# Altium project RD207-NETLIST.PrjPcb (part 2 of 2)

## Sheet 7.SchDoc
size 420 x 297 mm
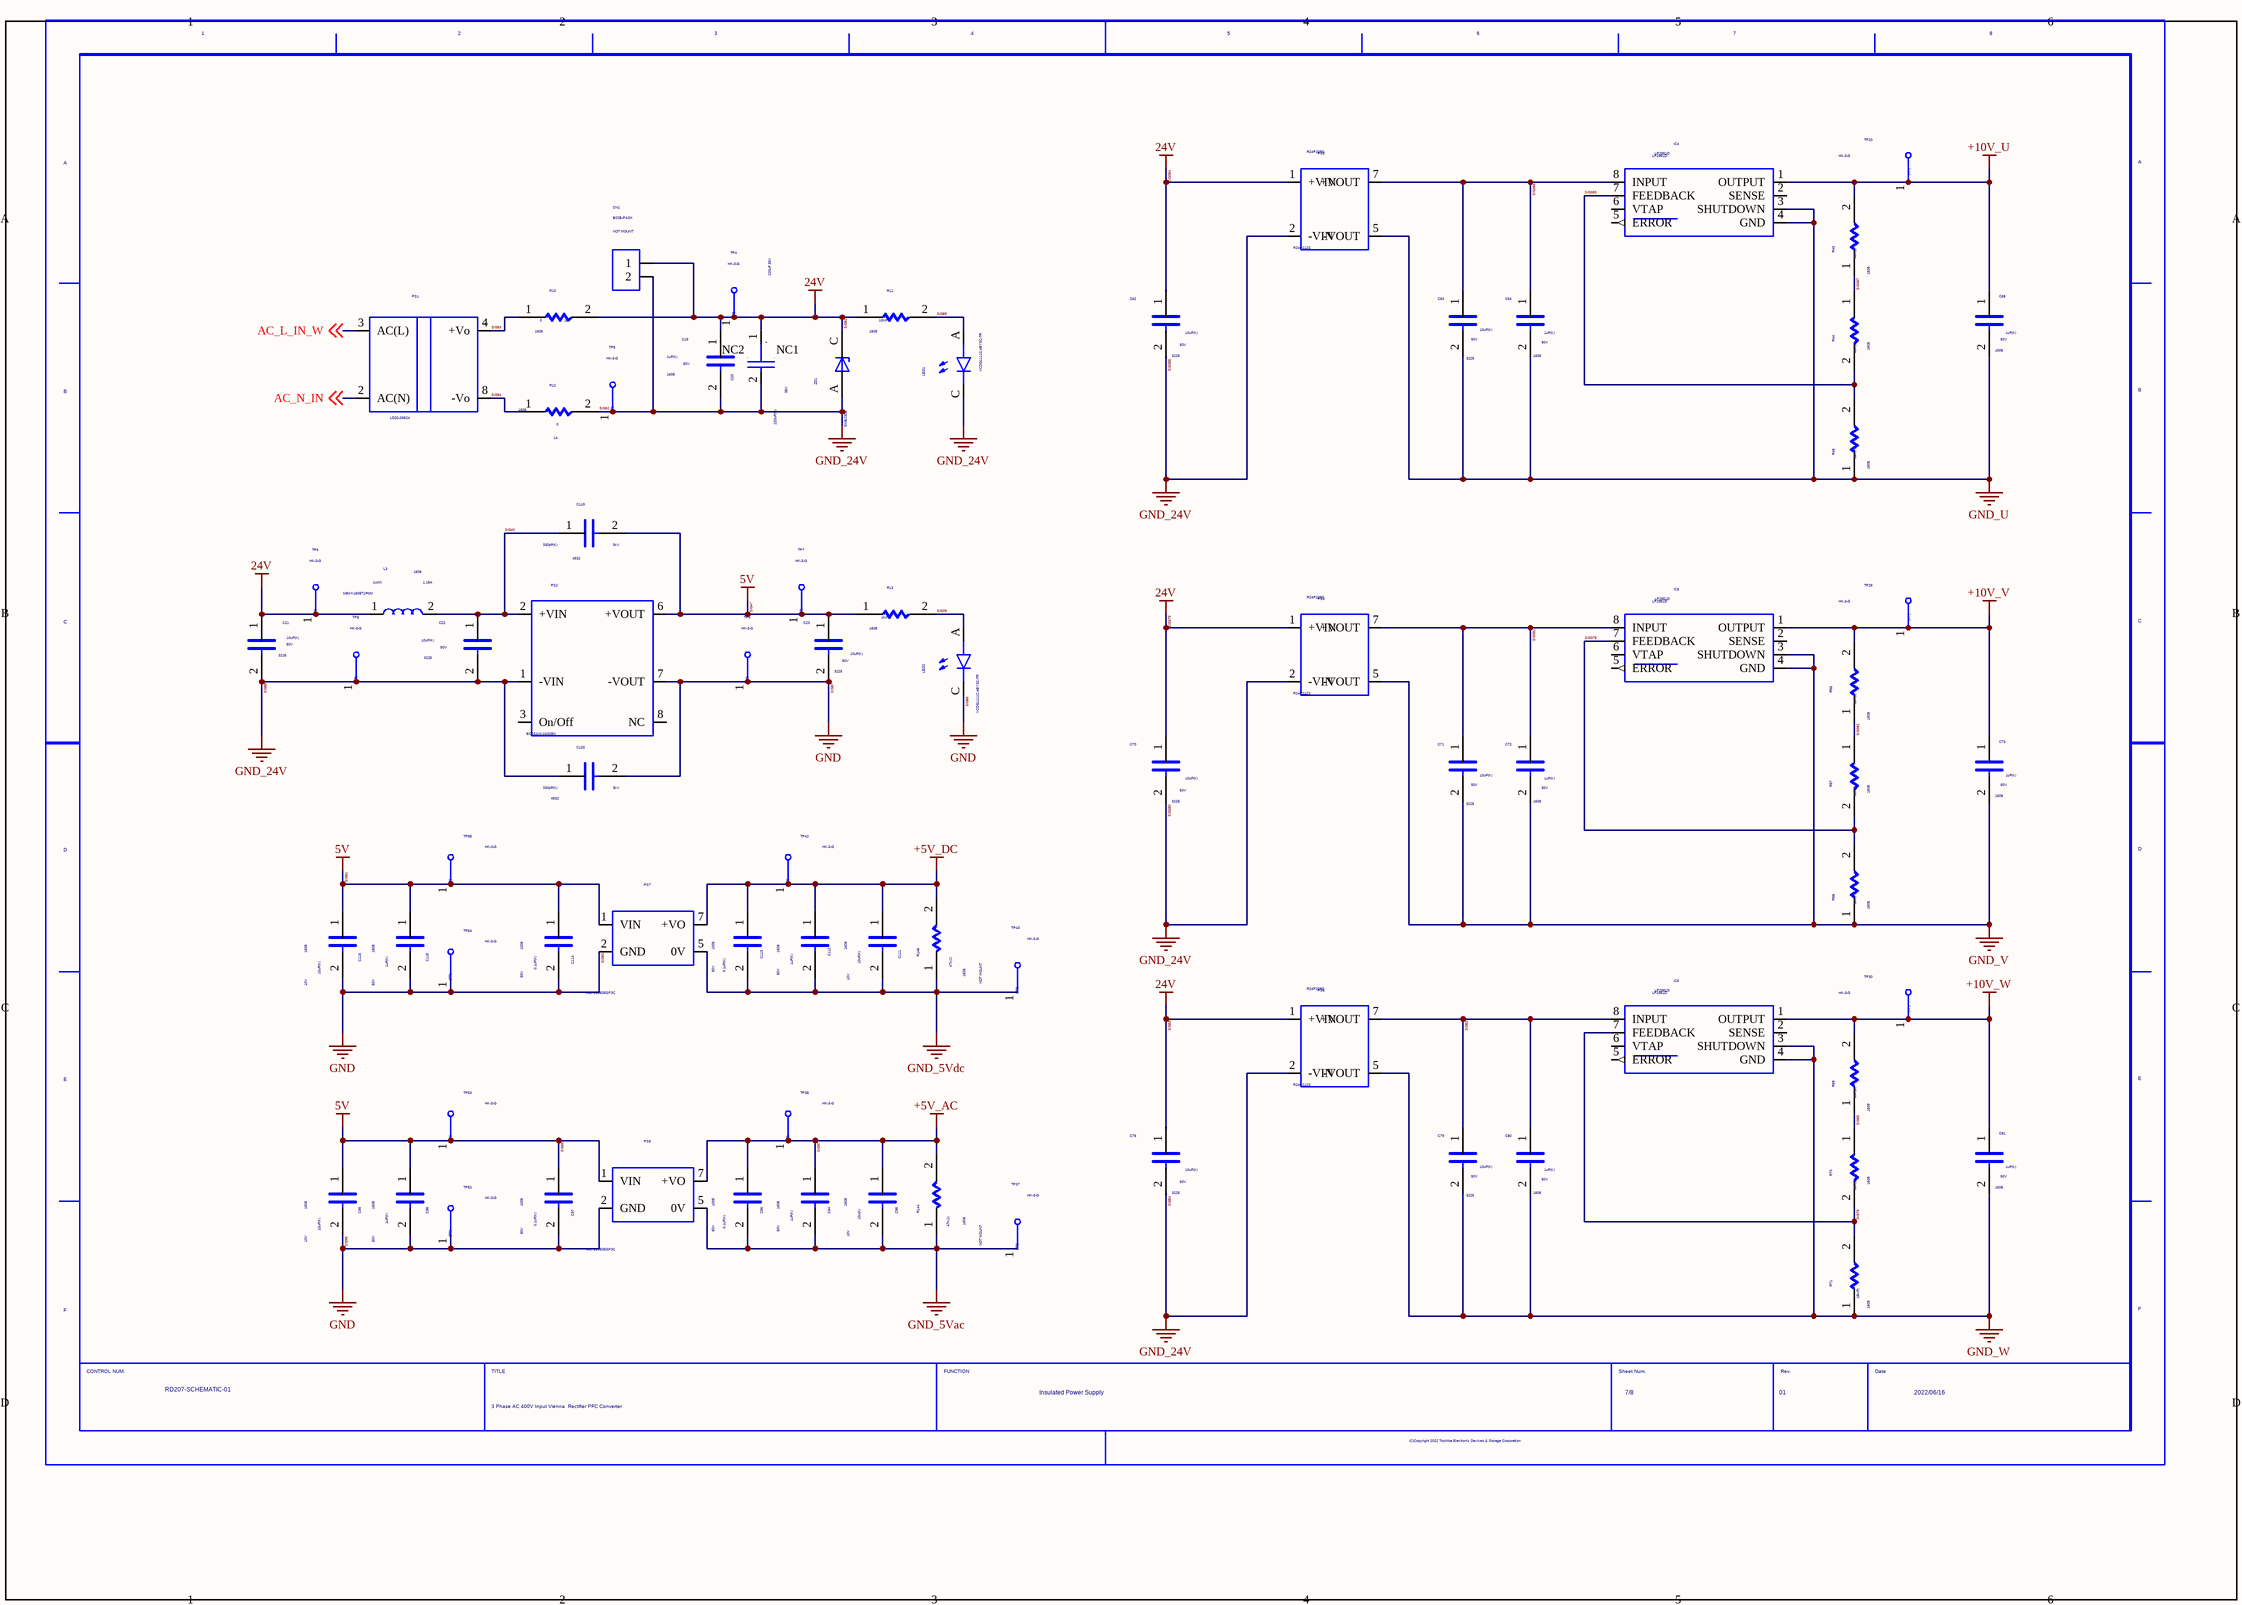
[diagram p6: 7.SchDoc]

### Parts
(Parts that share a designator on the sheet are numbered #1, #2 ... from top to bottom, then left to right.)
C19  SIZECODESMD: 1608  VAL2: 50V  VAL1: 1uF(K)  (hidden comment: C)
C20  NOTE: 220uF 35V  VAL2: 35V  VAL1: 220uF(M)  (hidden comment: MAL216099001E3)
C21  SIZECODESMD: 3225  VAL2: 50V  VAL1: 10uF(K)  (hidden comment: C)
C22  SIZECODESMD: 3225  VAL2: 50V  VAL1: 10uF(K)  (hidden comment: C)
C23  SIZECODESMD: 3225  VAL2: 50V  VAL1: 10uF(K)  (hidden comment: C)
C62  SIZECODESMD: 3225  VAL2: 50V  VAL1: 10uF(K)  (hidden comment: C)
C63  SIZECODESMD: 3225  VAL2: 50V  VAL1: 10uF(K)  (hidden comment: C)
C64  SIZECODESMD: 1608  VAL2: 50V  VAL1: 1uF(K)  (hidden comment: C)
C65  SIZECODESMD: 1608  VAL2: 50V  VAL1: 1uF(K)  (hidden comment: C)
C70  SIZECODESMD: 3225  VAL2: 50V  VAL1: 10uF(K)  (hidden comment: C)
C71  SIZECODESMD: 3225  VAL2: 50V  VAL1: 10uF(K)  (hidden comment: C)
C72  SIZECODESMD: 1608  VAL2: 50V  VAL1: 1uF(K)  (hidden comment: C)
C73  SIZECODESMD: 1608  VAL2: 50V  VAL1: 1uF(K)  (hidden comment: C)
C78  SIZECODESMD: 3225  VAL2: 50V  VAL1: 10uF(K)  (hidden comment: C)
C79  SIZECODESMD: 3225  VAL2: 50V  VAL1: 10uF(K)  (hidden comment: C)
C80  SIZECODESMD: 1608  VAL2: 50V  VAL1: 1uF(K)  (hidden comment: C)
C81  SIZECODESMD: 1608  VAL2: 50V  VAL1: 1uF(K)  (hidden comment: C)
C94  SIZECODESMD: 1608  VAL2: 50V  VAL1: 1uF(K)  (hidden comment: C)
C95  SIZECODESMD: 1608  VAL2: 10V  VAL1: 10u(K)  (hidden comment: C)
C96  SIZECODESMD: 1005  VAL2: 50V  VAL1: 0.1uF(K)  (hidden comment: C)
C97  SIZECODESMD: 1005  VAL2: 50V  VAL1: 0.1uF(K)  (hidden comment: C)
C98  SIZECODESMD: 1608  VAL2: 50V  VAL1: 1uF(K)  (hidden comment: C)
C99  SIZECODESMD: 1608  VAL2: 10V  VAL1: 10uF(K)  (hidden comment: C)
C111  SIZECODESMD: 1608  VAL2: 10V  VAL1: 10uF(K)  (hidden comment: C)
C112  SIZECODESMD: 1608  VAL2: 50V  VAL1: 1uF(K)  (hidden comment: C)
C113  SIZECODESMD: 1005  VAL2: 50V  VAL1: 0.1uF(K)  (hidden comment: C)
C114  SIZECODESMD: 1005  VAL2: 50V  VAL1: 0.1uF(K)  (hidden comment: C)
C115  SIZECODESMD: 1608  VAL2: 50V  VAL1: 1uF(K)  (hidden comment: C)
C116  SIZECODESMD: 1608  VAL2: 10V  VAL1: 10uF(K)  (hidden comment: C)
C119  SIZECODESMD: 4532  VAL2: 3kV  VAL1: 330pF(K)  (hidden comment: C)
C120  SIZECODESMD: 4532  VAL2: 3kV  VAL1: 330pF(K)  (hidden comment: C)
CN1  NOTMOUNT: NOT MOUNT  (hidden comment: BM02B-PASS-1-TFT(LF)(SN))
IC4  LP2951D
IC5  LP2951D
IC6  LP2951D
L3  SIZECODESMD: 1608  VAL3: MBKK1608T1R0M  VAL2: 1.15A  VAL1: 1u(M)  (hidden comment: L)
LED1  VCDG1111C-4BY3C-TR
LED2  VCDG1111C-4BY3C-TR
PS1  LD20-26B24
PS2  EC5SAW-24S05N
PS3  R24P209D
PS4  R24P209D
PS5  R24P209D
PS6  MEF1S0505SP3C
PS7  MEF1S0505SP3C
R10  SIZECODESMD: 1608  VAL2: 1A  VAL1: 0  (hidden comment: R)
R11  SIZECODESMD: 1608  VAL1: 10k(F)  (hidden comment: R)
R12  SIZECODESMD: 1608  VAL2: 1A  VAL1: 0  (hidden comment: R)
R13  SIZECODESMD: 1608  VAL1: 1k(F)  (hidden comment: R)
R43  SIZECODESMD: 1608  VAL1: 68k(B)  (hidden comment: R)
R44  SIZECODESMD: 1608  VAL1: 68k(B)  (hidden comment: R)
R45  SIZECODESMD: 1608  VAL1: 18k(F)  (hidden comment: R)
R56  SIZECODESMD: 1608  VAL1: 68k(B)  (hidden comment: R)
R57  SIZECODESMD: 1608  VAL1: 68k(B)  (hidden comment: R)
R58  SIZECODESMD: 1608  VAL1: 18k(F)  (hidden comment: R)
R69  SIZECODESMD: 1608  VAL1: 68k(B)  (hidden comment: R)
R70  SIZECODESMD: 1608  VAL1: 68k(B)  (hidden comment: R)
R71  SIZECODESMD: 1608  VAL1: 18k(F)  (hidden comment: R)
R144  NOTMOUNT: NOT MOUNT  SIZECODESMD: 1608  VAL1: 47k(J)  (hidden comment: R)
R145  NOTMOUNT: NOT MOUNT  SIZECODESMD: 1608  VAL1: 47k(J)  (hidden comment: R)
TP4  VAL3: HK-3-G  (hidden comment: TP)
TP5  VAL3: HK-3-G  (hidden comment: TP)
TP6  VAL3: HK-3-G  (hidden comment: TP)
TP7  VAL3: HK-3-G  (hidden comment: TP)
TP8  VAL3: HK-3-G  (hidden comment: TP)
TP9  VAL3: HK-3-G  (hidden comment: TP)
TP20  VAL3: HK-3-G  (hidden comment: TP)
TP25  VAL3: HK-3-G  (hidden comment: TP)
TP30  VAL3: HK-3-G  (hidden comment: TP)
TP35  VAL3: HK-3-G  (hidden comment: TP)
TP37  VAL3: HK-3-G  (hidden comment: TP)
TP42  VAL3: HK-3-G  (hidden comment: TP)
TP43  VAL3: HK-3-G  (hidden comment: TP)
TP52  VAL3: HK-3-G  (hidden comment: TP)
TP53  VAL3: HK-3-G  (hidden comment: TP)
TP54  VAL3: HK-3-G  (hidden comment: TP)
TP55  VAL3: HK-3-G  (hidden comment: TP)
U?#7  DATE: 2022/06/16  TITLE: 3 Phase AC 400V Input Vienna / Rectifier PFC Converter  REVISION: 01  SHEETNUMBER: 7/8  FUNCTION: Insulated Power Supply  DRAWINGNUMBER: RD207-SCHEMATIC-01  (hidden comment: WAKU_DEF100)
ZD1  VAL3: SMBJ30A  (hidden comment: ZD)

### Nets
5V: C23.1 C97.1 C98.1 C99.1 C114.1 C115.1 C116.1 C119.2 PS2.6(+VOUT) PS6.1(VIN) PS7.1(VIN) R13.1 TP7.1 TP53.1 TP55.1  [also labelled SIG47, SIG81, SIG95]  [project net SIG104]
24V: C19.1 C20.1 C21.1 C62.1 C70.1 C78.1 CN1.1 L3.1 PS3.1(+VIN) PS4.1(+VIN) PS5.1(+VIN) R10.2 R11.1 TP4.1 TP6.1 ZD1.C  [also labelled SIG379, SIG384, SIG53, SIG91]  [project net SIG351]
+5V_AC: C94.1 C95.1 C96.1 PS6.7(+VO) R144.2 TP35.1  [also labelled SIG97]  [project net SIG153]
+5V_DC: C111.1 C112.1 C113.1 PS7.7(+VO) R145.2 TP42.1
+10V_U: C65.1 IC4.1(OUTPUT) R43.2 TP20.1  [project net SIG287]
+10V_V: C73.1 IC5.1(OUTPUT) R56.2 TP25.1
+10V_W: C81.1 IC6.1(OUTPUT) R69.2 TP30.1
GND: C23.2 C97.2 C98.2 C99.2 C114.2 C115.2 C116.2 C120.2 LED2.C PS2.7(-VOUT) PS6.2(GND) PS7.2(GND) TP9.1 TP52.1 TP54.1  [also labelled SIG83, SIG86, SIG87, SIG96]  [project net SIG105]
GND_5Vac: C94.2 C95.2 C96.2 PS6.5(0V) R144.1 TP37.1
GND_5Vdc: C111.2 C112.2 C113.2 PS7.5(0V) R145.1 TP43.1
GND_24V: C19.2 C20.2 C21.2 C22.2 C62.2 C70.2 C78.2 C120.1 CN1.2 LED1.C PS2.1(-VIN) PS3.2(-VIN) PS4.2(-VIN) PS5.2(-VIN) R12.2 TP5.1 TP8.1 ZD1.A  [also labelled SIG380, SIG385, SIG54, SIG88, SIG92]  [project net SIG348]
GND_U: C63.2 C64.2 C65.2 IC4.3(SHUTDOWN) IC4.4(GND) PS3.5(-VOUT) R45.1
GND_V: C71.2 C72.2 C73.2 IC5.3(SHUTDOWN) IC5.4(GND) PS4.5(-VOUT) R58.1
GND_W: C79.2 C80.2 C81.2 IC6.3(SHUTDOWN) IC6.4(GND) PS5.5(-VOUT) R71.1
AC_L_IN_W: PS1.3(AC(L)) ; off-sheet AC_L_IN_W
AC_N_IN: PS1.2(AC(N)) ; off-sheet AC_N_IN
SIG39: LED2.A R13.2
SIG40: C22.1 C119.1 L3.2 PS2.2(+VIN)
SIG52: C79.1 C80.1 IC6.8(INPUT) PS5.7(+VOUT)
SIG55: R69.1 R70.1
SIG75: IC6.7(FEEDBACK) R70.2 R71.2
SIG89: LED1.A R11.2
SIG93: PS1.4(+Vo) R10.1
SIG94: PS1.8(-Vo) R12.1
SIG378: IC5.7(FEEDBACK) R57.2 R58.2
SIG381: C71.1 C72.1 IC5.8(INPUT) PS4.7(+VOUT)
SIG382: R56.1 R57.1
SIG383: IC4.7(FEEDBACK) R44.2 R45.2
SIG386: C63.1 C64.1 IC4.8(INPUT) PS3.7(+VOUT)
SIG387: R43.1 R44.1

Not connected (* = marked no-connect by the designer): C20 NC1 NC2; IC4 2(SENSE) 5(ERROR) 6(VTAP); IC5 2(SENSE) 5(ERROR) 6(VTAP); IC6 2(SENSE) 5(ERROR) 6(VTAP); PS2 3(On/Off) 8(NC)

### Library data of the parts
C19 C64 C65 C72 C73 C80 C81 C94 C98 C112 C115 = C: OriginalSymbolOrigin: (2540,7620); COMP: -C-UMK107AB7105KA-T
C20 = MAL216099001E3: Aluminum,35V,±20%; MANUFACTURER: Vishay; COMP: -C-MAL216099001E3; TIME: 11:39:41; UPDATEUSER: t5459927; UPDATETIME: 17:02:27; SAVECOUNT: 2; SAVEAREA0: -15593,-10586,20389,5809; OriginalSymbolOrigin: (0,0)
C21-C23 C62 C63 C70 C71 C78 C79 = C: OriginalSymbolOrigin: (2540,7620); COMP: -C-UMK325AB7106KM-T
C95 C99 C111 C116 = C: OriginalSymbolOrigin: (2540,7620); COMP: -C-GRM188D71A106KA73D
C96 C97 C113 C114 = C: OriginalSymbolOrigin: (2540,7620); COMP: -C-UMK105BJ104KV-F
C119 C120 = C: OriginalSymbolOrigin: (2540,7620); COMP: -C-C4532CH3F331K250KA
CN1 = B02B-PASK: Connector, 250V, 3A; MANUFACTURER: JST; COMP: -CN-NC_B02B-PASK; NOTE: 2pin; TIME: 11:39:42; UPDATEUSER: t5459927; UPDATETIME: 16:50:18; SAVECOUNT: 6; SAVEAREA0: -5711,-10440,12954,3224; OriginalSymbolOrigin: (0,0)
IC4-IC6 = LP2951D: Voltage Regulators; MANUFACTURER: Txsas Instruments; COMP: -IC-LP2951D; TIME: 16:53:55; UPDATEUSER: t5459927; UPDATETIME: 16:15:29; SAVECOUNT: 3; SAVEAREA0: -15946,-25147,36340,13186; OriginalSymbolOrigin: (0,0)
L3 = L: OriginalSymbolOrigin: (2540,5080); COMP: -L-MBKK1608T1R0M
LED1 LED2 = VCDG1111C_4BY3C_TR: LED; MANUFACTURER: STANLEY; COMP: -LED-VCDG1111C-4BY3C-TR_AC; NOTE: Green; TIME: 11:39:41; UPDATEUSER: t5459927; SAVECOUNT: 1; OriginalSymbolOrigin: (0,-2540); SIZECODESMD: 1608; INSTANCENAME: INS17056102
PS1 = LD20_26B24: AC/DC Converter; MANUFACTURER: Mornsun; COMP: PS-LD20-26B24; TIME: 11:39:42; UPDATEUSER: t5459927; UPDATETIME: 17:04:57; SAVECOUNT: 2; SAVEAREA0: -3533,-18371,23278,1256; OriginalSymbolOrigin: (0,0)
PS2 = EC5SAW_24S05N: DC/DC Converter; MANUFACTURER: CINCON; COMP: PS-EC5SAW-24S05N; TIME: 11:39:40; UPDATEUSER: t5459927; UPDATETIME: 14:27:04; SAVECOUNT: 4; SAVEAREA0: -8840,-26929,31144,2341; OriginalSymbolOrigin: (0,0)
PS3-PS5 = R24P212S: DC/DC Converter; MANUFACTURER: RECOM; COMP: -PS-R24P212S; TIME: 16:53:55; UPDATEUSER: t5459927; UPDATETIME: 16:30:09; SAVECOUNT: 6; SAVEAREA0: -9940,-15240,22833,0; OriginalSymbolOrigin: (0,0)
PS6 PS7 = MEF1S0505SP3C: DC/DC Converter; MANUFACTURER: MORNSUN; COMP: PS-MEF1S0505SP3C; TIME: 16:53:55; UPDATEUSER: t5459927; UPDATETIME: 13:45:31; SAVECOUNT: 4; SAVEAREA0: -2499,-12525,17820,2350; OriginalSymbolOrigin: (0,0)
R10 R12 = R: OriginalSymbolOrigin: (5080,5080); COMP: -R-RK73Z1JTTD
R11 = R: OriginalSymbolOrigin: (5080,5080); VAL2: 100mW; COMP: -R-ERJ3EKF1002V
R13 = R: OriginalSymbolOrigin: (5080,5080); VAL2: 125mW; COMP: -R-RK73H1JTTD1001F
R43 R44 R56 R57 R69 R70 = R: OriginalSymbolOrigin: (5080,5080); VAL2: 100mW; COMP: -R-ERJ3EKF6802V
R45 R58 R71 = R: OriginalSymbolOrigin: (5080,5080); VAL2: 100mW; COMP: -R-ERJ3EKF1802V
R144 R145 = R: OriginalSymbolOrigin: (5080,5080); COMP: -R-NC_R1608; VAL2: 100mW
TP4-TP9 TP20 TP25 TP30 TP35 TP37 TP42 TP43 TP52-TP55 = TP: TIME: 16:12:21; UPDATEUSER: fukuda-y; UPDATETIME: 16:18:11; SAVECOUNT: 2; SAVEAREA0: -242,-92,12810,7836; OriginalSymbolOrigin: (0,7620); COMP: -TP-HK-3-G
U?#7 = WAKU_DEF100: PLOTTIME: HH:MM; SAVEAREA0: 22200,72372,612276,319236; TIME: 14:30:25; UPDATEUSER: t5459927; UPDATETIME: 09:21:33; SAVECOUNT: 7; OriginalSymbolOrigin: (10160,284480)
ZD1 = ZD: SAVEAREA0: -4630,-153,17114,13055; TIME: 14:49:55; UPDATEUSER: fukuda-y; UPDATETIME: 08:18:42; SAVECOUNT: 6; OriginalSymbolOrigin: (5080,5080); COMP: -ZD-SMBJ30A_AC

## Sheet 8.SchDoc
size 420 x 297 mm
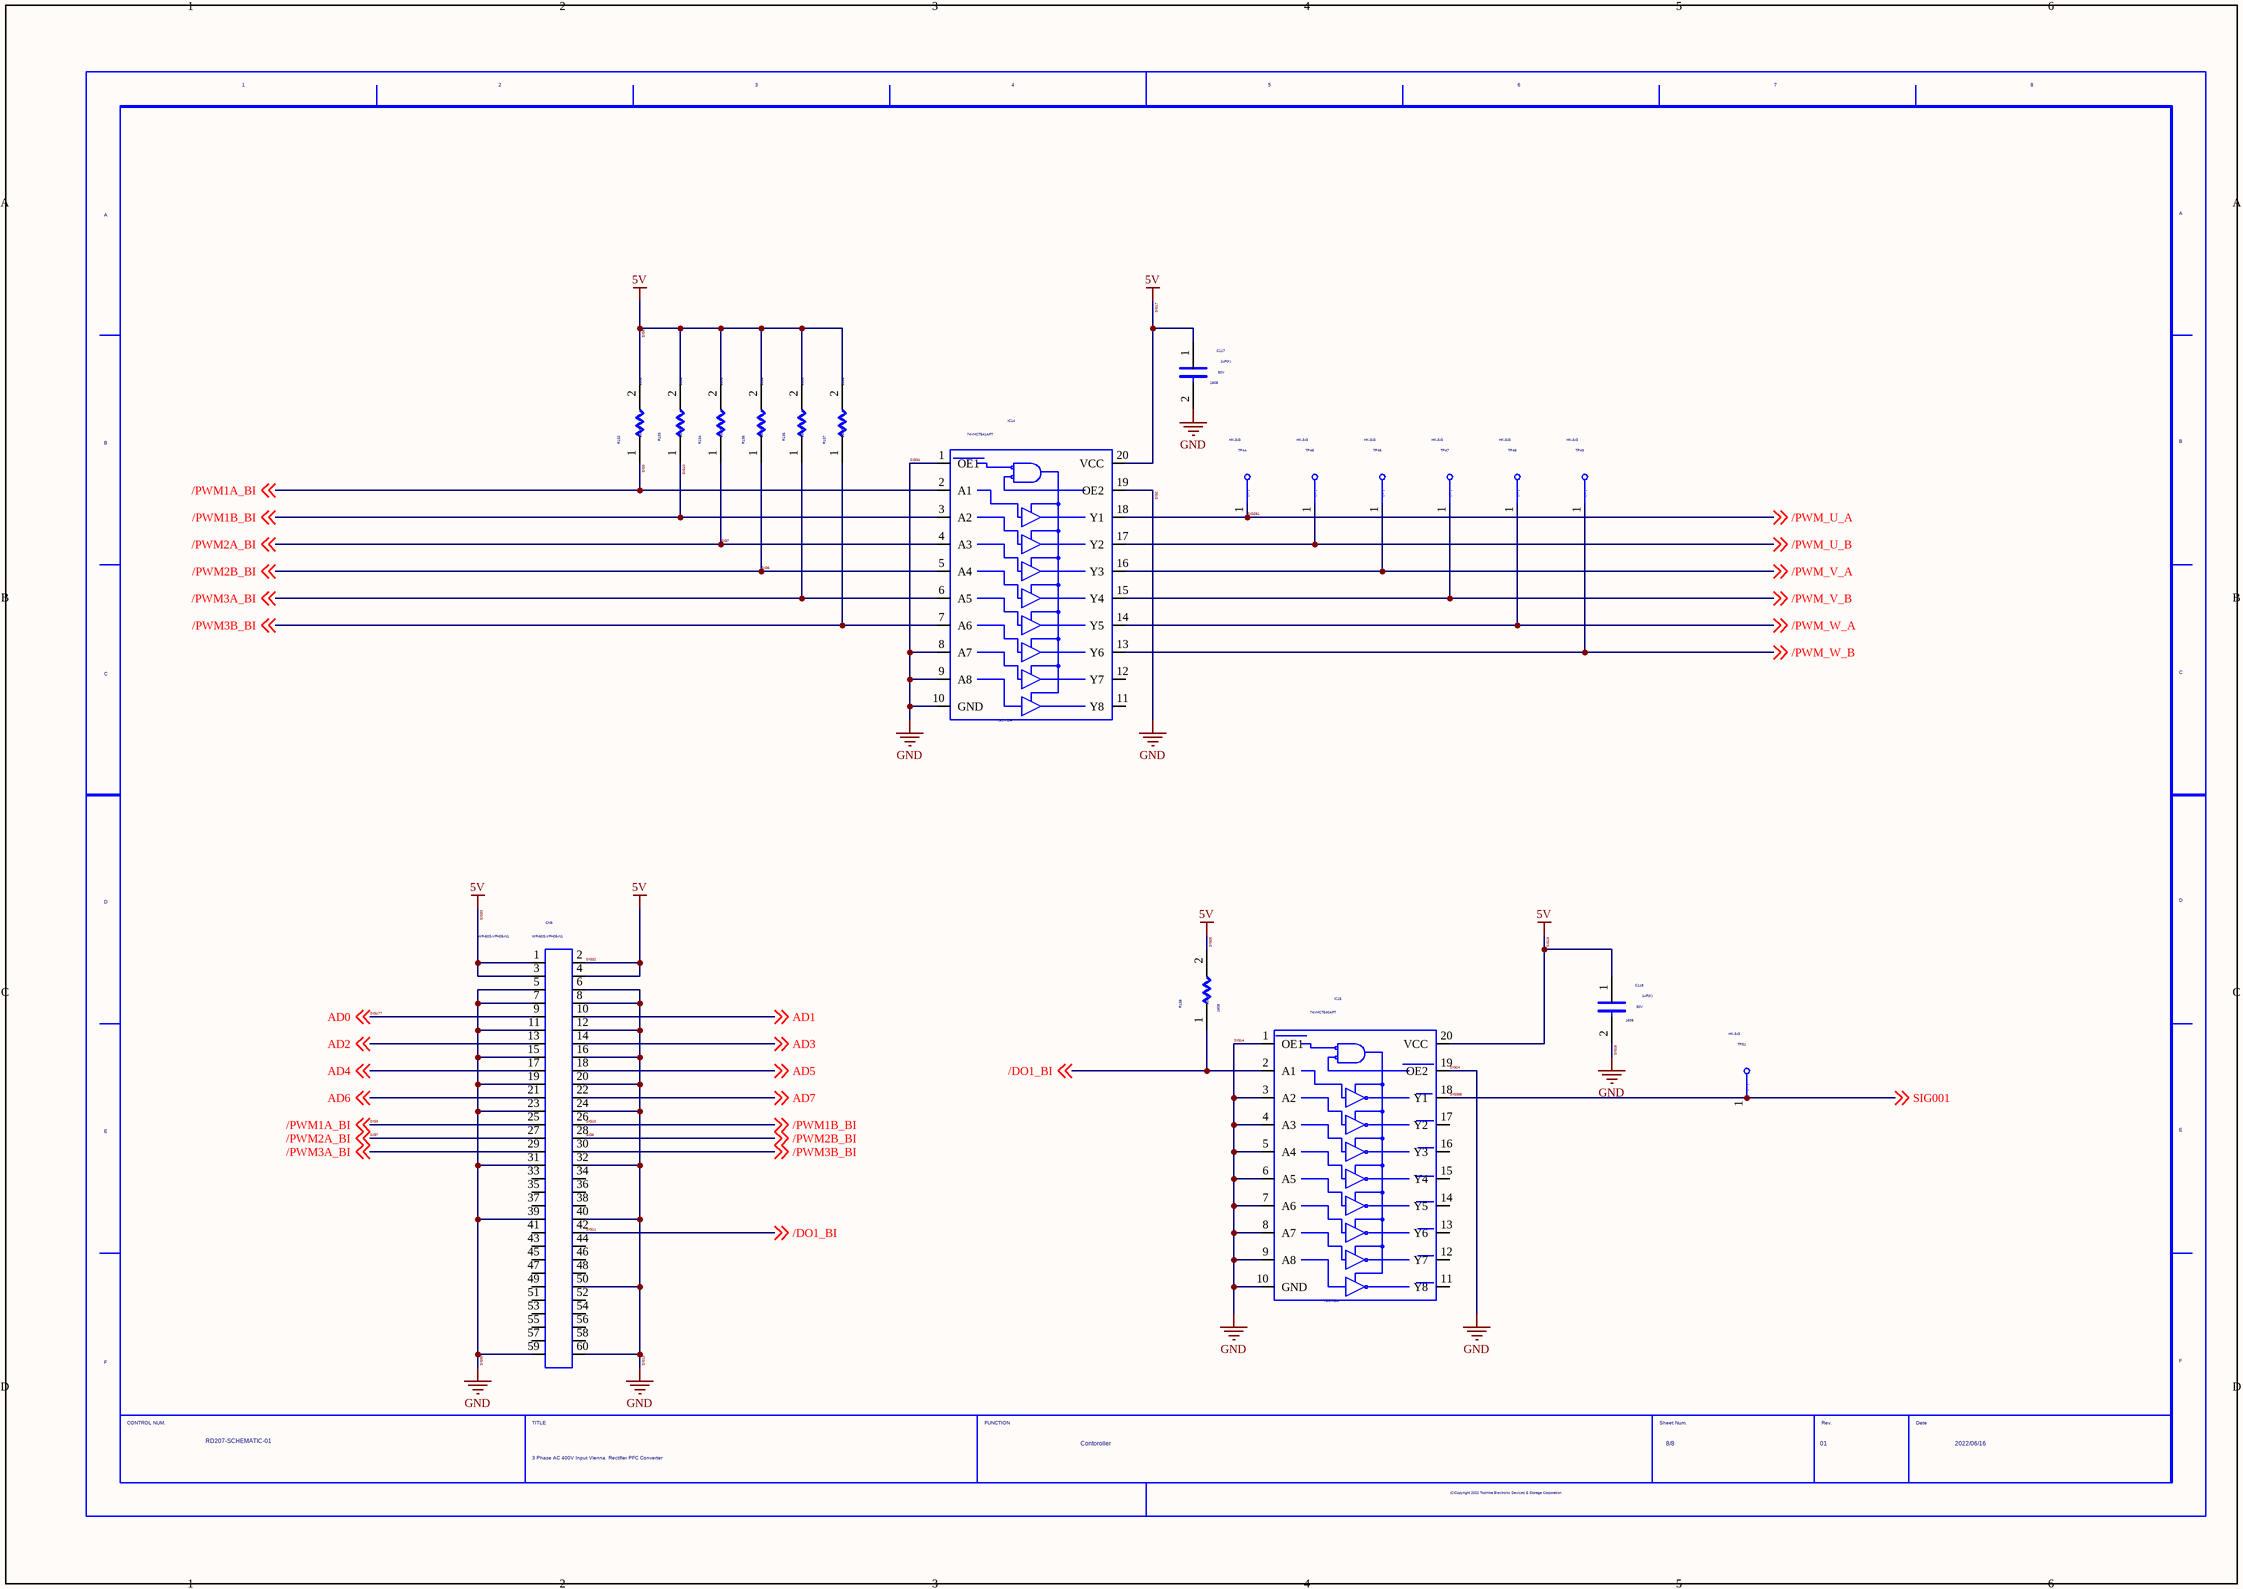
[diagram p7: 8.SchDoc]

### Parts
(Parts that share a designator on the sheet are numbered #1, #2 ... from top to bottom, then left to right.)
C117  SIZECODESMD: 1608  VAL2: 50V  VAL1: 1uF(K)  (hidden comment: C)
C118  SIZECODESMD: 1608  VAL2: 50V  VAL1: 1uF(K)  (hidden comment: C)
CN9  WR-60S-VFH05-N1
IC14  USERCOMPTEXT3: TOSHIBA  VAL3: 74VHCT541AFT  (hidden comment: 74VHC541FT)
IC15  USERCOMPTEXT3: TOSHIBA  VAL3: 74VHCT540AFT  (hidden comment: 74VHC540FT)
R132  SIZECODESMD: 1608  VAL1: 10k(F)  (hidden comment: R)
R133  SIZECODESMD: 1608  VAL1: 10k(F)  (hidden comment: R)
R134  SIZECODESMD: 1608  VAL1: 10k(F)  (hidden comment: R)
R135  SIZECODESMD: 1608  VAL1: 10k(F)  (hidden comment: R)
R136  SIZECODESMD: 1608  VAL1: 10k(F)  (hidden comment: R)
R137  SIZECODESMD: 1608  VAL1: 10k(F)  (hidden comment: R)
R138  SIZECODESMD: 1608  VAL1: 10k(F)  (hidden comment: R)
TP44  VAL3: HK-3-G  (hidden comment: TP)
TP45  VAL3: HK-3-G  (hidden comment: TP)
TP46  VAL3: HK-3-G  (hidden comment: TP)
TP47  VAL3: HK-3-G  (hidden comment: TP)
TP48  VAL3: HK-3-G  (hidden comment: TP)
TP49  VAL3: HK-3-G  (hidden comment: TP)
TP51  VAL3: HK-3-G  (hidden comment: TP)
U?#8  DATE: 2022/06/16  TITLE: 3 Phase AC 400V Input Vienna / Rectifier PFC Converter  REVISION: 01  SHEETNUMBER: 8/8  FUNCTION: Contoroller  DRAWINGNUMBER: RD207-SCHEMATIC-01  (hidden comment: WAKU_DEF100)

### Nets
5V: C117.1 C118.1 CN9.1 CN9.2 CN9.3 CN9.4 IC14.20(VCC) IC15.20(VCC) R132.2 R133.2 R134.2 R135.2 R136.2 R137.2 R138.2  [also labelled SIG17, SIG19, SIG25, SIG32, SIG33, SIG9]  [project net SIG104]
GND: C117.2 C118.2 CN9.5 CN9.6 CN9.7 CN9.8 CN9.11 CN9.12 CN9.15 CN9.16 CN9.19 CN9.20 CN9.23 CN9.24 CN9.31 CN9.32 CN9.39 CN9.40 CN9.50 CN9.59 CN9.60 IC14.1(OE1) IC14.8(A7) IC14.9(A8) IC14.10(GND) IC14.19(OE2) IC15.1(OE1) IC15.3(A2) IC15.4(A3) IC15.5(A4) IC15.6(A5) IC15.7(A6) IC15.8(A7) IC15.9(A8) IC15.10(GND) IC15.19(OE2)  [also labelled SIG13, SIG14, SIG15, SIG2, SIG24, SIG30, SIG34]  [project net SIG105]
/PWM3A_BI: CN9.29 IC14.6(A5) R136.1 ; off-sheet /PWM3A_BI
/PWM3B_BI: CN9.30 IC14.7(A6) R137.1 ; off-sheet /PWM3B_BI
/PWM_U_B: IC14.17(Y2) TP45.1 ; off-sheet /PWM_U_B
/PWM_V_A: IC14.16(Y3) TP46.1 ; off-sheet /PWM_V_A
/PWM_V_B: IC14.15(Y4) TP47.1 ; off-sheet /PWM_V_B
/PWM_W_A: IC14.14(Y5) TP48.1 ; off-sheet /PWM_W_A
/PWM_W_B: IC14.13(Y6) TP49.1 ; off-sheet /PWM_W_B
AD1: CN9.10 ; off-sheet AD1
AD2: CN9.13 ; off-sheet AD2
AD3: CN9.14 ; off-sheet AD3
AD4: CN9.17 ; off-sheet AD4
AD5: CN9.18 ; off-sheet AD5
AD6: CN9.21 ; off-sheet AD6
AD7: CN9.22 ; off-sheet AD7
SIG3: CN9.25 IC14.2(A1) R132.1 ; off-sheet /PWM1A_BI  [also labelled /PWM1A_BI]
SIG6: CN9.28 IC14.5(A4) R135.1 ; off-sheet /PWM2B_BI  [also labelled /PWM2B_BI]
SIG7: CN9.27 IC14.4(A3) R134.1 ; off-sheet /PWM2A_BI  [also labelled /PWM2A_BI]
SIG10: CN9.26 IC14.3(A2) R133.1 ; off-sheet /PWM1B_BI  [also labelled /PWM1B_BI]
SIG11: CN9.42 IC15.2(A1) R138.1 ; off-sheet /DO1_BI  [also labelled /DO1_BI]
SIG177: CN9.9 ; off-sheet AD0  [also labelled AD0]
SIG281: IC14.18(Y1) TP44.1 ; off-sheet /PWM_U_A  [also labelled /PWM_U_A]
SIG365: IC15.18(Y1) TP51.1 ; off-sheet SIG001  [also labelled SIG001]

Not connected (* = marked no-connect by the designer): CN9 33 34 35 36 37 38 41 43 44 45 46 47 48 49 51 52 53 54 55 56 57 58; IC14 11(Y8) 12(Y7); IC15 11(Y8) 12(Y7) 13(Y6) 14(Y5) 15(Y4) 16(Y3) 17(Y2)

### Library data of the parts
C117 C118 = C: as C19 on sheet 7
CN9 = WR_60S_VFH05_N1: Terminal, 200V, 0.3A; MANUFACTURER: JAE; COMP: -CN-WR-60S-VFH05-N1; NOTE: 60pin; TIME: 16:53:54; UPDATEUSER: t5459927; UPDATETIME: 14:46:38; SAVECOUNT: 2; SAVEAREA0: -56595,-80318,58967,4405; OriginalSymbolOrigin: (0,0)
IC14 = 74VHC541FT_0: Buffer; COMP: -IC-74VHCT541AFT; TIME: 16:53:58; UPDATEUSER: t5459927; UPDATETIME: 14:50:23; SAVECOUNT: 2; SAVEAREA0: -22847,-24597,51708,30063; OriginalSymbolOrigin: (0,0)
IC15 = 74VHC540FT: Buffer; COMP: -IC-74VHCT540AFT; TIME: 16:53:55; UPDATEUSER: t5459927; UPDATETIME: 14:48:47; SAVECOUNT: 2; SAVEAREA0: -22628,-27657,51926,27001; OriginalSymbolOrigin: (0,0)
R132-R138 = R: as R11 on sheet 7
TP44-TP49 TP51 = TP: as TP4-TP9 on sheet 7
U?#8 = WAKU_DEF100: as U?#7 on sheet 7

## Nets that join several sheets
+5V_DC: 5 (6 pins), 7 (6 pins)
+10V_V: 3 (C66.1 C68.1 PC3.6 PC4.6), 7 (C73.1 IC5.1 R56.2 TP25.1)
+10V_W: 3 (C74.1 C76.1 PC5.6 PC6.6), 7 (C81.1 IC6.1 R69.2 TP30.1)
GND_5Vac: 4 (6 pins), 7 (6 pins)
GND_5Vdc: 5 (6 pins), 7 (6 pins)
GND_U: 2 (6 pins), 3 (10 pins), 7 (7 pins)
GND_V: 2 (6 pins), 3 (10 pins), 7 (7 pins)
GND_W: 2 (6 pins), 3 (10 pins), 7 (7 pins)
SIG104: 2 (9 pins), 3 (6 pins), 4 (16 pins), 5 (12 pins), 6 (25 pins), 7 (15 pins), 8 (15 pins)
SIG105: 1 (PC7.3 R142.1), 2 (9 pins), 4 (20 pins), 5 (20 pins), 6 (28 pins), 7 (15 pins), 8 (36 pins)
SIG153: 4 (6 pins), 7 (6 pins)
SIG287: 3 (C58.1 C60.1 PC1.6 PC2.6), 7 (C65.1 IC4.1 R43.2 TP20.1)
SIG348: 1 (5 pins), 7 (18 pins)
SIG351: 1 (11 pins), 7 (16 pins)
/PWM_U_B: 3 (PC2.3 R40.2), 8 (IC14.17 TP45.1)
/PWM_V_A: 3 (PC3.3 R48.2), 8 (IC14.16 TP46.1)
/PWM_V_B: 3 (PC4.3 R53.2), 8 (IC14.15 TP47.1)
/PWM_W_A: 3 (PC5.3 R61.2), 8 (IC14.14 TP48.1)
/PWM_W_B: 3 (PC6.3 R66.2), 8 (IC14.13 TP49.1)
AC_L_IN_W: 1 (L2.6 R9.2 RLY3.4 RLY3.5), 7 (PS1.3)
AC_N_IN: 1 (L2.4 R6.2 RLY2.4 RLY2.5), 7 (PS1.2)
AC_U: 1 (6 pins), 2 (CT1.3 CT1.4), 4 (R75.1)
AC_V: 1 (6 pins), 2 (CT2.3 CT2.4), 4 (8 pins)
AD1: 4 (IC18.1 IC18.4 TP34.1), 8 (CN9.10)
AD2: 5 (IC21.1 IC21.4 TP38.1), 8 (CN9.13)
AD3: 5 (IC23.1 IC23.4 TP41.1), 8 (CN9.14)
AD4: 6 (IC31.3 IC31.4 TP13.1), 8 (CN9.17)
AD5: 6 (IC33.3 IC33.4 TP14.1), 8 (CN9.18)
AD6: 6 (IC35.3 IC35.4 TP15.1), 8 (CN9.21)
AD7: 6 (IC2.1 IC2.4 TP10.1), 8 (CN9.22)
Gate_U_A: 2 (CN2.S Q1.G), 3 (5 pins)
Gate_U_B: 2 (CN3.S Q2.G), 3 (5 pins)
Gate_V_A: 2 (CN4.S Q3.G), 3 (5 pins)
Gate_V_B: 2 (CN5.S Q4.G), 3 (5 pins)
Gate_W_A: 2 (CN6.S Q5.G), 3 (5 pins)
Gate_W_B: 2 (CN7.S Q6.G), 3 (5 pins)
lu: 2 (CT1.7), 6 (R23.1)
lv: 2 (CT2.7), 6 (R25.1)
lw: 2 (CT3.7), 6 (R26.2)
SIG177: 4 (IC16.1 IC16.4 TP31.1), 8 (CN9.9)
SIG281: 3 (PC1.3 R35.2), 8 (IC14.18 TP44.1)
SIG360: 1 (6 pins), 2 (CT3.3 CT3.4), 4 (R87.1)
SIG365: 1 (R141.1), 8 (IC15.18 TP51.1)
SIG374: 4 (IC10.3 IC20.3), 6 (6 pins)
Vdc_M: 2 (21 pins), 5 (8 pins)
Vdc_N: 2 (17 pins), 5 (R117.1)
Vdc_P: 2 (14 pins), 5 (R105.1)
Vref_in_u: 2 (CT1.6), 6 (6 pins)
Vref_in_v: 2 (CT2.6), 6 (6 pins)
Vref_in_w: 2 (CT3.6), 6 (6 pins)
